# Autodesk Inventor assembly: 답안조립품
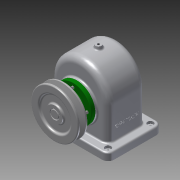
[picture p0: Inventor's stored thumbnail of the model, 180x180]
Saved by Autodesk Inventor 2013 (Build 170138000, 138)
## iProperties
Created: 2016-10
Part Number: 답안조립품
Document SubType Name: Assembly
Designer: cad10
Author: cad10
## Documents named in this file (14)
- C:\Documents and Settings\cad10\바탕 화면\461008V1001\답안조립품.iam
- C:\Documents and Settings\cad10\바탕 화면\461008V1001\부품1.ipt
- C:\Documents and Settings\cad10\바탕 화면\461008V1001\축.ipt
- C:\Documents and Settings\cad10\바탕 화면\461008V1001\키 - 6 x 6 x 22.ipt
- C:\Documents and Settings\cad10\바탕 화면\461008V1001\베어링 6203.ipt
- C:\Documents and Settings\cad10\바탕 화면\461008V1001\부시.ipt
- C:\Documents and Settings\cad10\바탕 화면\461008V1001\오일씰 28 40 8.ipt
- C:\Documents and Settings\cad10\바탕 화면\461008V1001\멈춤나사 - M4x10.ipt
- C:\Documents and Settings\cad10\바탕 화면\461008V1001\V-벨트풀리.ipt
- C:\Documents and Settings\cad10\바탕 화면\461008V1001\앞커버.ipt
- C:\Documents and Settings\cad10\바탕 화면\461008V1001\뒤커버.ipt
- C:\Documents and Settings\cad10\바탕 화면\461008V1001\볼트 M3 x 8.ipt
- C:\Documents and Settings\cad10\바탕 화면\461008V1001\볼트 M3 x 10.ipt
- C:\Documents and Settings\cad10\바탕 화면\461008V1001\스퍼기어.ipt
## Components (9 placed, 3 different names)
1. V-벨트풀리:2 — 각도:2
2. ISO 4762 M3 x 8:1
3. ISO 4762 M3 x 8:2
4. ISO 4762 M3 x 8:3
5. ISO 4762 M3 x 8:4
6. ISO 4762 M3 x 10:1
7. ISO 4762 M3 x 10:2
8. ISO 4762 M3 x 10:3
9. ISO 4762 M3 x 10:4
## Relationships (1: Angle 1)
- 각도:2 [Angle]: V-벨트풀리:2
